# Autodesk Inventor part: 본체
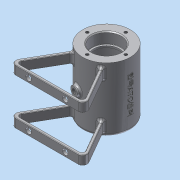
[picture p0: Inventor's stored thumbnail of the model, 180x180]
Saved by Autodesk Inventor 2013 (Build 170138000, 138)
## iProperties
Created: 2016-03
Part Number: 본체
Material: 알루미늄 6061
Document SubType Name: Modeling
Designer: Administrator
Mass: 211.864 g
Surface Area: 336.958 cm^2
Volume: 78.1787 cm^3
Density: 2.71 g/cm^3
Author: Administrator
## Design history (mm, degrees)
sketch "스케치1"
  geometry: C1 r 26 at (0, 0); 1 further point
  constraints: 1 centre point, 1 coincident
  dimensions: "d0" = 52 diameter of C1
extrude "돌출1" new body sketch "스케치1" stored distance "d1" = 70; taper "d2" = 0 deg
hole "구멍1" diameter "d5" = 28; stored, may be unused: countersink angle "d9" = 90 deg, drill point angle "d11" = 0 deg; dims "d3" = 10, "d4" = 10, "d6" = 6, "d7" = 32, "d8" = 12, "d10" = 14
hole "구멍2" diameter "d14" = 42; stored, may be unused: countersink angle "d18" = 90 deg, drill point angle "d20" = 0 deg; dims "d12" = 10, "d13" = 10, "d15" = 6, "d16" = 42, "d17" = 12, "d19" = 42
sketch "스케치2"
  geometry: C1 r 16 at (0, 0) reference; 1 further point
  constraints: 1 vertical alignment
  dimensions: "d21" = 21 distance of C1.centre point (0, 21)
hole "구멍3" sketch "스케치2" at (0, 21) diameter "d22" = 3.242; stored, may be unused: countersink angle "d26" = 90 deg, drill point angle "d28" = 118 deg; dims "d23" = 8, "d24" = 42, "d25" = 12, "d27" = 10
chamfer "모따기1" distance "d32" = 1; stored, may be unused: second distance "d33" = 2, angle "d34" = 45 deg
fillet "모깎기1" dims "d35" = 0.3
node "작업 평면1"
sketch "스케치4"
  geometry: L1 (-16.613, -20)-(-42.594, -65); L2 (-42.594, -65)-(42.594, -65); L3 (42.594, -65)-(16.613, -20); L4 (0, 0)-(0, -35.846); C1 r 16 at (0, 0) reference; C2 r 1.621 at (21, 0) reference; C3 r 1.621 at (0, -21) reference; C4 r 1.621 at (-21, 0) reference; C5 r 1.621 at (0, 21) reference; A1 r 26 centre (0, 0) between (-16.613, -20) and (16.613, -20) reference; 1 further point
  constraints: 8 end point, 2 point on circle, 1 equal length, 1 horizontal, 1 perpendicular
  dimensions: "d39" = 65 distance from line of point (0, 0) L2; "d40" = 30 deg angle of L1 L4; "d41" = 30 deg angle of L3 L4; "d42" = 45 distance from line of L3.end L2
extrude "돌출2" join sketch "스케치4" distance "d43" = 10; taper "d44" = 0 deg
sketch "스케치5"
  geometry: L1 (-16.613, -20)-(-42.594, -65) reference; L2 (-42.594, -65)-(42.594, -65) reference; L3 (42.594, -65)-(16.613, -20) reference; L4 (-37.398, -62)-(-14.183, -21.791); L5 (14.183, -21.791)-(37.398, -62); L6 (37.398, -62)-(-37.398, -62); A1 r 26 centre (0, 0) between (-16.613, -20) and (16.613, -20) reference; A2 r 29 centre (0, 0) between (-15.685, -24.392) and (15.685, -24.392)
  constraints: 6 end point, 4 point on circle, 2 point on line, 1 centre point
  dimensions: "d45" = 3 distance between parallel lines of L1 L4; "d68" = 3 distance between parallel lines of L3 L5; "d69" = 3 distance between parallel lines of L2 L6
extrude "돌출3" cut sketch "스케치5" distance "d46" = 10; taper "d47" = 0 deg
sketch "스케치6"
  geometry: L1 (0, 0)-(85.188, 0) reference; L2 (85.188, -10)-(0, -10) reference; L3 (42.594, -10)-(42.594, 0); 2 further points
  constraints: 2 end point, 2 midpoint
  dimensions: "d49" = 20 distance from line of L3 point (22.594, -5); "d50" = 5 distance from line of L2 point (22.594, -5)
node "작업 평면2"
sketch "스케치7"
  geometry: L1 (26, 35)-(-26, 35) reference; C1 r 5 at (0, 0); 1 further point
  constraints: 1 centre point, 1 coincident
  dimensions: "d52" = 10 diameter of C1
extrude "돌출4" join sketch "스케치7" stored distance "d53" = 3; taper "d54" = 0 deg
hole "구멍4" diameter "d57" = 5.188; stored, may be unused: countersink angle "d61" = 90 deg, drill point angle "d63" = 0 deg; dims "d55" = 10, "d56" = 10, "d58" = 6, "d59" = 4, "d60" = 2, "d62" = 8
fillet "모깎기3" dims "d64" = 5, "d65" = 3
fillet "모깎기4" dims "d66" = 0.5
fillet "모깎기5" dims "d67" = 0.5
fillet "모깎기6" dims "d70" = 3
fillet "모깎기7" dims "d74" = 2
hole "구멍5" sketch "스케치6" diameter "d75" = 6; stored, may be unused: countersink angle "d79" = 90 deg, drill point angle "d81" = 0 deg; dims "d76" = 6, "d77" = 4, "d78" = 2, "d80" = 8
node "작업 평면3"
sketch "스케치8"
  geometry: L1 (26, 35)-(-26, 35) reference; L2 (26, -35)-(26, 35) reference; 2 further points
  constraints: 1 other
  dimensions: "d88" = 35 distance from line of L1 point (0, 0); "d89" = 26 distance from line of L2 point (0, 0)
feature "엠보싱1" sketch "스케치8" dims "d90" = 0.5, "d91" = 0
fillet "모깎기8" dims "d92" = 3
node "솔리드1"
pattern_circular "원형 패턴1" dims angle "d30" = 360 deg
mirror "대칭1"
mirror "대칭2"
pattern_circular "원형 패턴2" dims angle "d72" = 165 deg
pattern_linear "직사각형 패턴1" dims "d84" = 40
node "절단 모서리 투영2"
other parameters: "d51" = 29
